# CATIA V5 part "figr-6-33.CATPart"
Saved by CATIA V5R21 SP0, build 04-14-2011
Part number: Part1
Bounding box of the stored display mesh (mm): x -43 to 43, y -66.608 to 66.608, z -13.545 to 13.545
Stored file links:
  D:\CATIA V5R21 E-RESOURCES\CATIA-V5R21\catia-v5r21-prt\c06-catia-v5r21-prt\c06-catia-v5r21-figr-6-33.CATPart
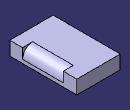
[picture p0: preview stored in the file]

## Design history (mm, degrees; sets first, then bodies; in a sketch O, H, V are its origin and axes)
Body1 (main body)
  Sketch1 on yz-plane, origin (0, 0, 0), H (0, 1, 0), V (0, 0, 1)
    line L1 (-66.6077, 13.5449) -> (66.6077, 13.5449)
    line L2 (66.6077, 13.5449) -> (66.6077, -13.5449)
    line L3 (66.6077, -13.5449) -> (-66.6077, -13.5449)
    line L4 (-66.6077, -13.5449) -> (-66.6077, 13.5449)
    axis line L5 (66.6077, -13.5449) -> (-66.6077, 13.5449)
    horizontal: L1 H, L3 H
    vertical: L2 V, L4 V
    midpoint: O L5
  Pad1: profile Sketch1, direction (1, 0, 0), length 43, mirrored extent
  Fillet1: radius 20, on edge [face of Pad1 | face of Pad1]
